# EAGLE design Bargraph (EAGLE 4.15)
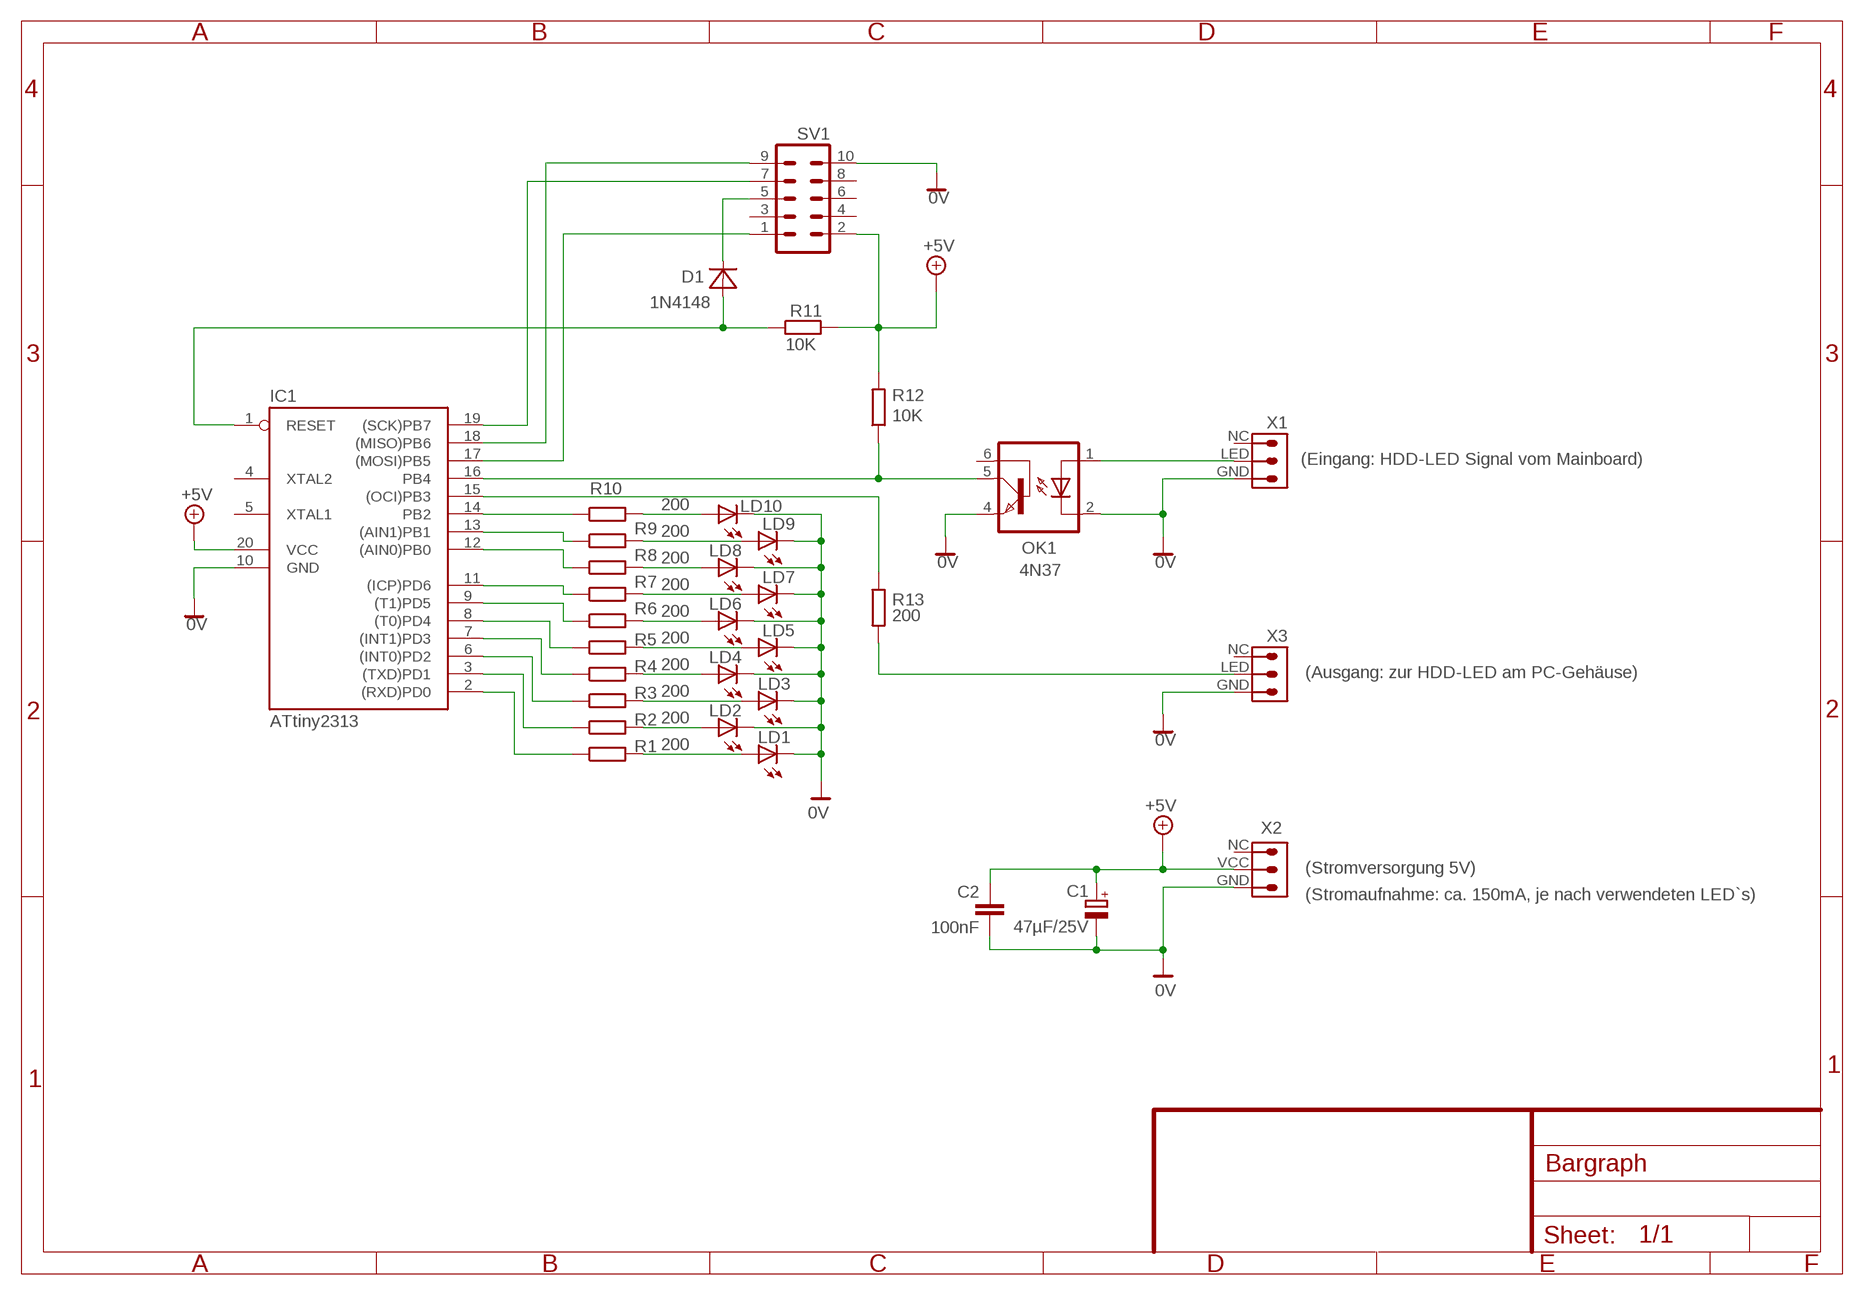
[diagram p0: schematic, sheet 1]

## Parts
C1  47µF/25V  CPOL-EUE2.5-5  [E2,5-5]
C2  100nF  C-EUC1206  [C1206]
D1  1N4148  [DO35/7.5]
IC1  ATtiny2313  AT90S2313S  [SO20L]
LD1  LED3MM  [LED3MM]
LD2  LED3MM  [LED3MM]
LD3  LED3MM  [LED3MM]
LD4  LED3MM  [LED3MM]
LD5  LED3MM  [LED3MM]
LD6  LED3MM  [LED3MM]
LD7  LED3MM  [LED3MM]
LD8  LED3MM  [LED3MM]
LD9  LED3MM  [LED3MM]
LD10  LED3MM  [LED3MM]
OK1  4N37  [DIL06]
R1  200  R-EU_R1206  [R1206]
R2  200  R-EU_R1206  [R1206]
R3  200  R-EU_R1206  [R1206]
R4  200  R-EU_R1206  [R1206]
R5  200  R-EU_R1206  [R1206]
R6  200  R-EU_R1206  [R1206]
R7  200  R-EU_R1206  [R1206]
R8  200  R-EU_R1206  [R1206]
R9  200  R-EU_R1206  [R1206]
R10  200  R-EU_R1206  [R1206]
R11  10K  R-EU_R1206  [R1206]
R12  10K  R-EU_R1206  [R1206]
R13  200  R-EU_R1206  [R1206]
SV1  ML10L  [ML10L]
X1  MOLEX_3PIN_1  [MOLEX_3PIN_1]
X2  MOLEX_3PIN  [MOLEX_3PIN]
X3  MOLEX_3PIN_1  [MOLEX_3PIN_1]

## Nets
0V: C1.- C2.2 IC1.10(GND) LD1.K(C) LD2.K(C) LD3.K(C) LD4.K(C) LD5.K(C) LD6.K(C) LD7.K(C) LD8.K(C) LD9.K(C) LD10.K(C) OK1.2(C) OK1.4(EMI) SV1.10 X1.GND X2.GND X3.GND
+5V: C1.+ C2.1 IC1.20(VCC) R11.2 R12.2 SV1.2 X2.VCC
N$1: IC1.18((MISO)PB6) SV1.9
N$2: IC1.19((SCK)PB7) SV1.7
N$3: IC1.17((MOSI)PB5) SV1.1
N$4: IC1.16(PB4) OK1.5(COL) R12.1
N$5: D1.A IC1.1(RESET) R11.1
N$6: D1.C SV1.5
N$7: IC1.2((RXD)PD0) R1.1
N$8: IC1.3((TXD)PD1) R2.1
N$9: IC1.6((INT0)PD2) R3.1
N$10: IC1.7((INT1)PD3) R4.1
N$11: IC1.8((T0)PD4) R5.1
N$12: IC1.9((T1)PD5) R6.1
N$13: IC1.11((ICP)PD6) R7.1
N$14: IC1.14(PB2) R10.1
N$15: IC1.13((AIN1)PB1) R9.1
N$16: IC1.12((AIN0)PB0) R8.1
N$17: LD10.A R10.2
N$18: LD9.A R9.2
N$19: LD8.A R8.2
N$20: LD7.A R7.2
N$21: LD6.A R6.2
N$22: LD5.A R5.2
N$23: LD4.A R4.2
N$24: LD3.A R3.2
N$25: LD2.A R2.2
N$26: LD1.A R1.2
N$27: OK1.1(A) X1.LED
N$32: IC1.15((OCI)PB3) R13.1
N$33: R13.2 X3.LED
Unconnected: IC1.4(XTAL2) IC1.5(XTAL1) OK1.6(BAS) SV1.3 SV1.4 SV1.6 SV1.8 X1.NC X2.NC X3.NC

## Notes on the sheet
- (Eingang: HDD-LED Signal vom Mainboard)
- (Ausgang: zur HDD-LED am PC-Gehäuse)
- (Stromversorgung 5V)
- (Stromaufnahme: ca. 150mA, je nach verwendeten LED`s)

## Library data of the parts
C1 = RCL_Neu:CPOL-EU: POLARIZED CAPACITOR, European symbol
C2 = RCL_Neu:C-EU: CAPACITOR, European symbol
D1 = Eigene:1N4148: Kleinsignaldiode
IC1 = avr:AT90S2313: MICROCONTROLLER 2 Kbytes FLASH 128 bytes SRAM 128 bytes EEPROM UART
LD1-LD10 = led2:LED: LED
OK1 = optocoupler-2:4N37: MOTOROLA OPTO COUPLER
R1-R13 = RCL_Neu:R-EU_: RESISTOR, European symbol
SV1 = con-harting-ml:ML10: HARTING
X1 X3 = Eigene_misc:MOLEX_3PIN_1
X2 = Eigene_misc:MOLEX_3PIN: 3PIN Molexstecker für 12V Lüfter

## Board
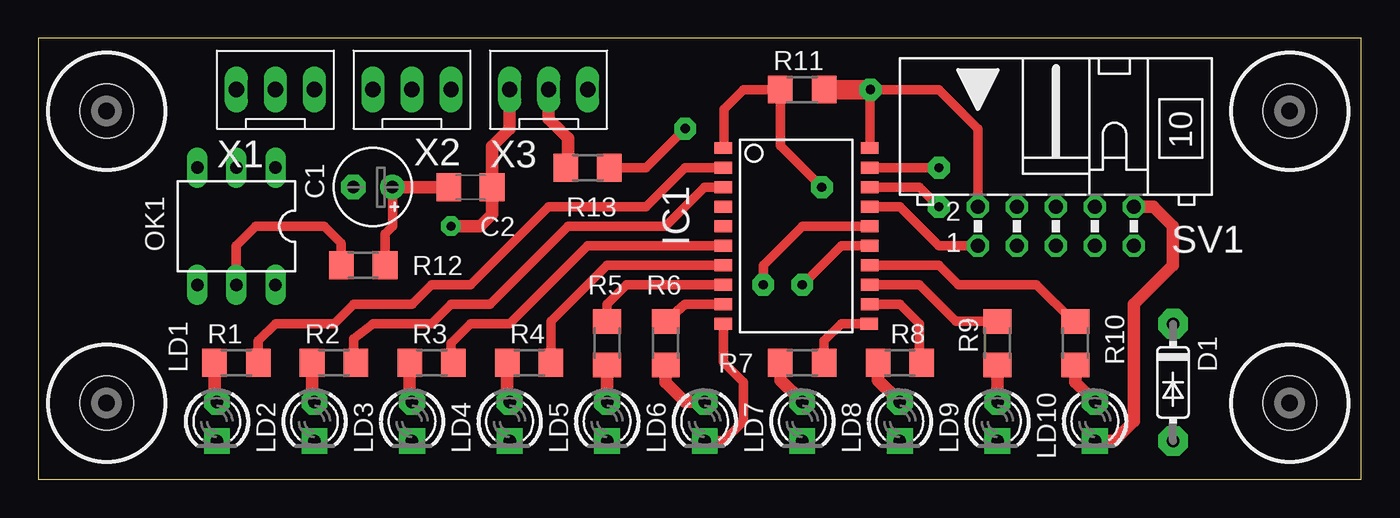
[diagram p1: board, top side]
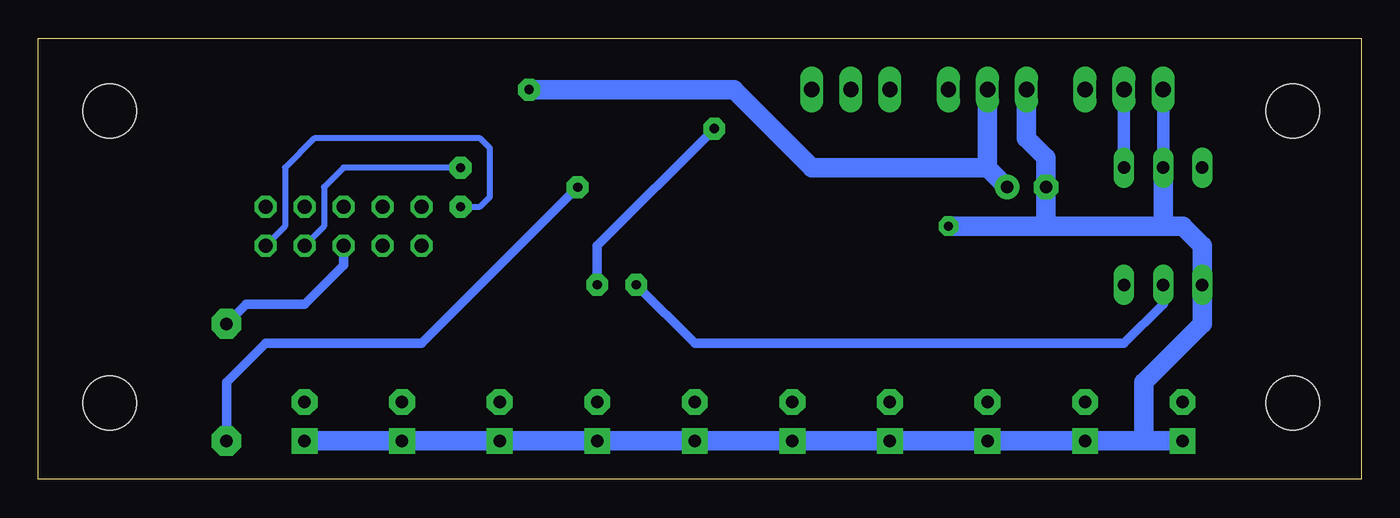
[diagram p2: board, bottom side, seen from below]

Size 86.09 x 28.69 mm. Coordinates in mm from the lower left corner, seen from the top.
Outline: 0,0 86.09,0 86.09,28.69 0,28.69 0,0
Copper layers (1*16): Top 0.035mm / dielectric 1.5mm / Bottom 0.035mm
Design rules "default": minimum track width 10mil, minimum drill 20mil, track to track 8mil, track to pad 8mil, pad to pad 8mil, via to via 8mil, smd to smd 8mil, copper to edge 40mil, drill to drill 8mil, minimum pad ring 10mil, minimum via ring 8mil, stop-mask expansion 4mil, vias tented up to drill 0mil, thermal gap 10mil

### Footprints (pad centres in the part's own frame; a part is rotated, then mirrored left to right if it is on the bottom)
E2,5-5 = drill 0.813 pad 1.6 round: + -1.27,0 | drill 0.813 pad 1.6 octagon: - 1.27,0
C1206 = smd 1.6 x 1.8: 1 -1.4,0; 2 1.4,0
DO35/7.5 = drill 0.813 pad 1.93 octagon: A 3.81,0; C -3.81,0
SO20L = smd 0.762 x 1.143: 1 -5.08,-5.131; 2 -3.81,-5.131; 3 -2.54,-5.131; 4 -1.27,-5.131; 5 0,-5.131; 6 1.27,-5.131; 7 2.54,-5.131; 8 3.81,-5.131; 9 5.08,-5.131; 10 6.35,-5.131; 11 6.35,4.369; 12 5.08,4.394; 13 3.81,4.394; 14 2.54,4.394; 15 1.27,4.394; 16 0,4.394; 17 -1.27,4.394; 18 -2.54,4.394; 19 -3.81,4.394; 20 -5.08,4.394
LED3MM = drill 0.813 pad 1.676 octagon: A -1.27,0 | drill 0.813 pad 1.676 square: K 1.27,0
DIL06 = drill 0.813 long: 1 -2.54,-3.81; 2 0,-3.81; 3 2.54,-3.81; 4 2.54,3.81; 5 0,3.81; 6 -2.54,3.81
R1206 = smd 1.6 x 1.803: 1 -1.422,0; 2 1.422,0
ML10L = drill 0.914 octagon: 1 -5.08,-1.27; 2 -5.08,1.27; 3 -2.54,-1.27; 4 -2.54,1.27; 5 0,-1.27; 6 0,1.27; 7 2.54,-1.27; 8 2.54,1.27; 9 5.08,-1.27; 10 5.08,1.27
DRIL-3,5 = hole 3.5: 0,0
MOLEX_3PIN_1 = drill 1 long: GND -2.54,0; LED 0,0; NC 2.54,0
MOLEX_3PIN = drill 1 long: GND -2.54,0; NC 2.54,0; VCC 0,0

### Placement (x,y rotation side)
C1  21.77,19.01 180 top
C2  28.12,19.01 0 top
D1  73.84,6.31 270 top
IC1  49.72,16.47 270 top
LD1  11.62,3.77 270 top
LD2  17.96,3.77 270 top
LD3  24.31,3.77 270 top
LD4  30.66,3.77 270 top
LD5  37.02,3.77 270 top
LD6  43.37,3.77 270 top
LD7  49.72,3.77 270 top
LD8  56.07,3.77 270 top
LD9  62.41,3.77 270 top
LD10  68.77,3.77 270 top
OK1  12.88,16.47 180 top
R1  12.88,7.58 180 top
R2  19.23,7.58 180 top
R3  25.58,7.58 180 top
R4  31.93,7.58 180 top
R5  37.02,8.85 270 top
R6  40.83,8.85 270 top
R7  49.72,7.58 180 top
R8  56.07,7.58 180 top
R9  62.41,8.85 270 top
R10  67.5,8.85 270 top
R11  49.72,25.36 0 top
R12  21.14,13.93 0 top
R13  35.75,20.28 180 top
SV1  66.23,16.47 0 top
U$1  [DRIL-3,5]  4.44,4.96 0 top
U$2  [DRIL-3,5]  4.44,23.96 0 top
U$3  [DRIL-3,5]  81.44,23.96 0 top
U$4  [DRIL-3,5]  81.44,4.96 0 top
X1  15.43,25.36 0 top
X2  24.31,25.36 0 top
X3  33.21,25.36 0 top

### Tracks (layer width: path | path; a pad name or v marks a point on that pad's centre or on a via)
0V  (via drill 0.6 pad 1.27)
  Top 0.61: IC1.10 44.58,7.63 45.91,6.31 45.91,3.77 44.64,2.5 LD6.K
  Top 0.813: SV1.10 72.58,17.74 73.84,16.47 73.84,13.93 71.31,11.39 71.31,3.77 70.03,2.5 LD10.K | v26.86,16.47 28.76,16.47 29.52,17.24 C2.2 29.52,21.68 30.66,22.82 X3.GND
  Bottom 0.813: OK1.2 X1.GND
  Bottom 1.27: LD10.K LD9.K LD8.K LD7.K LD6.K LD5.K LD4.K LD3.K LD2.K 14.16,2.5 | LD1.K 14.16,2.5 | 12.88,16.47 11.62,16.47 10.35,15.2 OK1.4 10.35,10.12 14.16,6.31 14.16,2.5 | 12.88,16.47 OK1.2 | 20.5,16.47 v26.86,16.47 | 20.5,16.47 C1.- 20.5,20.92 21.77,22.19 X2.GND | 12.88,16.47 20.5,16.47
+5V  (via drill 0.6 pad 1.42)
  Top 0.61: C1.+ 23.04,16.47 22.56,15.99 R12.2 | SV1.2 61.15,22.82 58.61,25.36 v54.16,25.36 | 54.11,25.36 IC1.20
  Top 0.813: C1.+ C2.1
  Top 1.27: v54.16,25.36 54.11,25.36 R11.2
  Bottom 1.27: v54.16,25.36 40.83,25.36 35.75,20.28 24.31,20.28 | C1.+ 24.31,20.28 | 24.31,20.28 X2.VCC
N$1  (via drill 0.6 pad 1.42)
  Top 0.61: IC1.18 57.34,19.01 v58.61,17.74
  Bottom 0.406: SV1.9 70.03,16.47 70.03,20.28 68.13,22.19 57.34,22.19 56.7,21.55 56.7,18.38 57.34,17.74 v58.61,17.74
N$2  (via drill 0.6 pad 1.42)
  Top 0.61: IC1.19 v58.61,20.28
  Bottom 0.406: v58.61,20.28 66.23,20.28 67.5,19.01 67.5,16.47 SV1.7
N$3
  Top 0.61: IC1.17 56.07,17.74 58.61,15.2 SV1.1
N$4  (via drill 0.6 pad 1.42)
  Top 0.61: v47.18,12.66 47.18,13.93 49.72,16.47 IC1.16 | R12.1 19.72,15.35 18.6,16.47 14.16,16.47 12.88,15.2 OK1.5
  Bottom 0.61: v47.18,12.66 43.37,8.85 15.43,8.85 12.88,11.39 OK1.5
N$5  (via drill 0.6 pad 1.42)
  Top 0.61: IC1.1 44.64,21.55 44.64,24.09 45.91,25.36 R11.1 48.29,21.7 v50.98,19.01
  Bottom 0.61: v50.98,19.01 61.15,8.85 71.31,8.85 73.84,6.31 D1.A
N$6
  Bottom 0.61: SV1.5 66.23,13.93 68.77,11.39 72.58,11.39 D1.C
N$7
  Top 0.61: R1.1 14.31,9 15.43,10.12 19.23,10.12 20.5,11.39 24.31,11.39 25.58,12.66 28.12,12.66 33.21,17.74 39.55,17.74 42.09,20.28 IC1.2 44.64,20.28
N$8
  Top 0.61: R2.1 20.66,7.73 20.5,7.58 20.5,9.16 21.77,10.12 25.58,10.12 26.86,11.39 29.39,11.39 34.48,16.47 40.83,16.47 43.37,19.01 IC1.3 44.64,19.01
N$9
  Top 0.61: R3.1 27.01,7.73 26.86,7.89 26.86,8.85 28.12,10.12 30.66,10.12 35.75,15.2 IC1.6 44.64,15.2
N$10
  Top 0.61: R4.1 33.36,10.27 37.02,13.93 IC1.7 44.64,13.93
N$11
  Top 0.61: R5.1 37.02,11.39 38.29,12.66 IC1.8
N$12
  Top 0.61: IC1.9 42.09,11.39 R6.1
N$13
  Top 0.61: R7.1 51.14,9 52.26,10.12 IC1.11
N$14
  Top 0.61: R10.1 67.34,10.27 64.95,12.66 59.88,12.66 58.61,13.93 IC1.14
N$15
  Top 0.61: IC1.13 57.34,12.66 59.72,10.27 R9.1
N$16
  Top 0.61: IC1.12 56.07,11.39 57.34,10.12 57.34,7.58 R8.1
N$17
  Top 0.813: R10.2 67.5,6.31 LD10.A
N$18
  Top 0.813: LD9.A R9.2
N$19
  Top 0.813: R8.2 54.64,6.46 LD8.A
N$20
  Top 0.813: R7.2 48.29,6.46 LD7.A
N$21
  Top 0.813: R6.2 40.83,6.31 42.09,5.04 LD6.A
N$22
  Top 0.813: LD5.A R5.2
N$23
  Top 0.813: R4.2 30.51,5.19 LD4.A
N$24
  Top 0.813: R3.2 24.16,5.19 LD3.A
N$25
  Top 0.813: R2.2 17.81,5.19 LD2.A
N$26
  Top 0.813: 11.46,5.19 R1.2
  Top 1.27: LD1.A 11.46,5.19
N$27
  Bottom 0.813: OK1.1 X1.LED
N$32  (via drill 0.6 pad 1.42)
  Top 0.61: IC1.15 52.26,15.2 v49.72,12.66 | R13.1 39.55,20.28 v42.09,22.82
  Bottom 0.61: v42.09,22.82 49.72,15.2 v49.72,12.66
N$33
  Top 0.813: R13.2 34.48,20.28 34.48,22.19 33.21,23.46 X3.LED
